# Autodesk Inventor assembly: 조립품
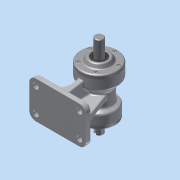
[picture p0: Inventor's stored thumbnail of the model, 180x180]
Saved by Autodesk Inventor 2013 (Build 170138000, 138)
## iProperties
Created: 2015-08
Part Number: 조립품
Document SubType Name: Assembly
Designer: Administrator
Author: Administrator
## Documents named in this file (10)
- C:\Users\Administrator\Desktop\450806V1013\조립품.iam
- C:\Users\Administrator\Desktop\450806V1013\M4x0.5.ipt
- C:\Users\Administrator\Desktop\450806V1013\뒤커버.ipt
- C:\Users\Administrator\Desktop\450806V1013\베어링 6203.ipt
- C:\Users\Administrator\Desktop\450806V1013\베어링 6205.ipt
- C:\Users\Administrator\Desktop\450806V1013\본체.ipt
- C:\Users\Administrator\Desktop\450806V1013\앞커버.ipt
- C:\Users\Administrator\Desktop\450806V1013\오일실 .ipt
- 오일실 .ipt
- C:\Users\Administrator\Desktop\450806V1013\축.ipt
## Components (10 placed, 1 different names)
1. M4x0.5:1
2. M4x0.5:2
3. M4x0.5:3
4. M4x0.5:4
5. M4x0.5:5
6. M4x0.5:6
7. M4x0.5:7
8. M4x0.5:8
9. M4x0.5:9
10. M4x0.5:10
